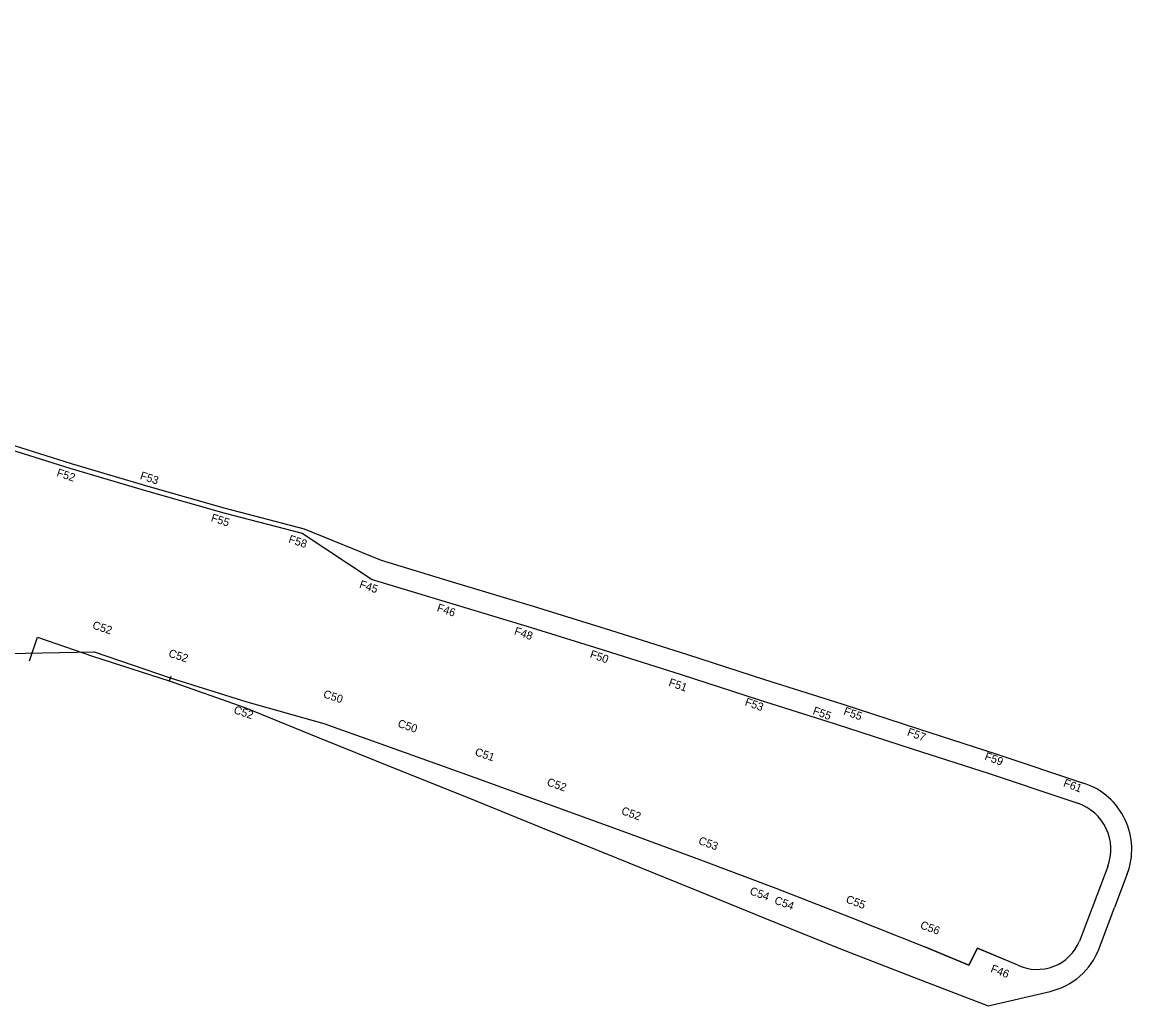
# Model space of a CAD drawing. Extents: x 2165700 to 2171741, y 206405 to 209505.
# Drawn here: x 2166493 to 2167183, y 208893 to 209504 of the extents above; entities that cross this region are included whole.
import ezdxf

# ---------------------------------------------------------------- set-up
doc = ezdxf.new("R2010")
doc.units = 0
for name, color, linetype in [('RD_PD_CstnLmt', 7, 'Continuous'), ('RD_PD_DR_ErosCtrl', 7, 'Continuous'), ('RD_PD_DR_FlowCtrl_TX', 7, 'Continuous'), ('RD_PD_TX_CstnLmt', 7, 'Continuous')]:
    doc.layers.add(name, color=color, linetype=linetype)

msp = doc.modelspace()

# ---------------------------------------------------------------- linework, layer by layer
at = {"layer": 'RD_PD_CstnLmt'}
for p, q in [((2167141.75, 209020.95), (2167149.19, 209018.43)), ((2167167.68, 208979.13), (2167150.21, 208932.82))]:
    msp.add_line(p, q, dxfattribs=at)
for points in [[(2166475.23, 209241.61), (2166522.74, 209226.69), (2166570.49, 209212.55), (2166618.56, 209198.92), (2166667.26, 209186.23), (2166710.66, 209157.58), (2166758.73, 209143.07), (2166806.82, 209128.55), (2166854.78, 209113.64), (2166902.66, 209098.43), (2166950.48, 209083.02), (2166998.41, 209067.87), (2167046.18, 209052.25), (2167094.06, 209036.89), (2167141.75, 209020.95)], [(2166484.54, 209111.46), (2166537.83, 209112.65), (2166585.21, 209096.41), (2166632.7, 209081.48), (2166680.67, 209067.96), (2166727.6, 209051.31), (2166774.46, 209034.46), (2166821.28, 209017.51), (2166868.09, 209000.55), (2166914.76, 208983.22), (2166961.38, 208965.78), (2167007.73, 208947.59), (2167053.99, 208929.2), (2167081.5, 208917.76), (2167086.85, 208928.42), (2167104.12, 208921.11)], [(2167111.84, 208917.84), (2167086.85, 208928.42), (2167081.5, 208917.76), (2167053.99, 208929.2), (2167054.19, 208929.17)]]:
    msp.add_lwpolyline(points, dxfattribs=at)
for centre, radius, start, end in [((2167139.54, 208989.89), 30.12, 339.06735, 71.31583), ((2167123.83, 208943.77), 28.56, 245.1896, 337.46341)]:
    msp.add_arc(centre, radius, start, end, dxfattribs=at)
at = {"layer": 'RD_PD_DR_ErosCtrl'}
for p in [(2167179.83, 208974.52), (2167162.37, 208928.23)]:
    msp.add_line(p, (2167171.94, 208953.59), dxfattribs=at)
for points in [[(2165776.16, 209503.85), (2165822.39, 209485.35), (2165868.6, 209466.86), (2165915.03, 209448.94), (2165961.43, 209430.93), (2166008.13, 209413.68), (2166054.58, 209395.77), (2166101.3, 209378.63), (2166147.93, 209361.21), (2166194.74, 209344.37), (2166241.75, 209327.99), (2166288.66, 209311.24), (2166335.34, 209293.94), (2166382.27, 209277.41), (2166429.19, 209260.78), (2166476.17, 209244.45), (2166523.61, 209229.56), (2166571.33, 209215.43), (2166619.35, 209201.82), (2166668.5, 209189), (2166668.5, 209189)], [(2166668.5, 209189), (2166716.24, 209169.48), (2166762.49, 209155.52), (2166810.63, 209140.98), (2166858.68, 209126.04), (2166906.62, 209110.81), (2166954.43, 209095.4), (2167002.39, 209080.25), (2167050.18, 209064.62), (2167098.11, 209049.24), (2167153.36, 209030.74)], [(2166497.83, 209107.06), (2166502.65, 209121.61), (2166536.94, 209109.92), (2166584.57, 209094.47), (2166584.57, 209094.47), (2166631.51, 209077.89), (2166677.7, 209059.15), (2166677.72, 209059.14), (2166723.95, 209040.53), (2166770.16, 209021.96), (2166816.32, 209003.28), (2166862.45, 208984.61), (2166908.56, 208965.91), (2166954.62, 208947.14), (2166954.62, 208947.14), (2167000.68, 208928.4), (2167046.96, 208910.29), (2167093.38, 208892.59), (2167131.86, 208901.52)]]:
    msp.add_lwpolyline(points, dxfattribs=at)
for centre, radius, start, end in [((2167139.54, 208989.89), 43.12, 339.11083, 71.31583), ((2167122.14, 208943.41), 43, 283.06291, 339.3321)]:
    msp.add_arc(centre, radius, start, end, dxfattribs=at)
at = {"layer": 'RD_PD_DR_FlowCtrl_TX'}
msp.add_line((2166585.5, 209097.32), (2166584.57, 209094.47), dxfattribs=at)

# ---------------------------------------------------------------- texts
at = {"layer": 'RD_PD_TX_CstnLmt'}
for s, rotation, p in [('F52', 341.65854, (2166514.22, 209221.84)), ('F53', 341.89727, (2166566.05, 209220.03)), ('F55', 341.97726, (2166610.1, 209193.85)), ('F58', 341.73852, (2166658.28, 209180.58)), ('F45', 341.49979, (2166702.31, 209152.54)), ('F46', 341.26106, (2166750.5, 209137.98)), ('C52', 341.89727, (2166536.46, 209127.13)), ('F48', 341.02233, (2166798.51, 209123.51)), ('C52', 341.97726, (2166583.7, 209109.68)), ('F50', 340.78359, (2166845.58, 209109.1)), ('F51', 340.54486, (2166894.46, 209091.6)), ('C50', 341.49979, (2166679.84, 209084.39)), ('F53', 340.30613, (2166941.86, 209079.48)), ('C52', 341.73852, (2166624.22, 209074.49)), ('F55', 340.0674, (2166984.01, 209074)), ('F55', 340.0674, (2167003.17, 209073.79)), ('C50', 341.26106, (2166726.12, 209066.08)), ('F57', 339.82866, (2167042.67, 209060.79)), ('C51', 341.02233, (2166774.09, 209048.39)), ('F59', 339.58993, (2167090.81, 209045.71)), ('C52', 340.78359, (2166818.78, 209029.69)), ('F61', 339.3512, (2167139.72, 209029.14)), ('C52', 340.54486, (2166865.05, 209011.79)), ('C53', 340.30613, (2166912.98, 208993.27)), ('C54', 340.0674, (2166944.81, 208962.01)), ('C54', 340.0674, (2166960.14, 208956.19)), ('C55', 339.82866, (2167004.59, 208956.86)), ('C56', 339.58993, (2167050.76, 208940.88)), ('F46', 339.3512, (2167094.53, 208913.76))]:
    msp.add_text(s, height=5, rotation=rotation, dxfattribs=at).set_placement(p)

doc.saveas('drawing.dxf')
